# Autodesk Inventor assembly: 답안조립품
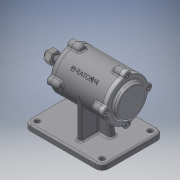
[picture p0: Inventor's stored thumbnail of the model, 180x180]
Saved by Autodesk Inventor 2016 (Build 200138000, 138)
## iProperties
Created: 2015-12
Part Number: 답안조립품
Document SubType Name: Assembly
Designer: Administrator
Author: Administrator
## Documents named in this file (11)
- D:\451208V1021\451208V1021\답안조립품.iam
- D:\451208V1021\451208V1021\본체.ipt
- D:\451208V1021\451208V1021\축.ipt
- D:\451208V1021\451208V1021\키(4 x 4 x 12).ipt
- D:\451208V1021\451208V1021\V-벨트풀리.ipt
- D:\451208V1021\451208V1021\너트 M12x1.25.ipt
- D:\451208V1021\451208V1021\베어링 6204.ipt
- D:\451208V1021\451208V1021\커버.ipt
- D:\451208V1021\451208V1021\오일실.ipt
- D:\451208V1021\451208V1021\커버2.ipt
- D:\451208V1021\451208V1021\볼트 M4 x 12.ipt
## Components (6 placed, 5 different names)
1. KS B 1311 (I) 4 x 4 x 12:1
2. V-벨트풀리:1
3. KS B 1012 클래스 1 일반 - 미터 M12x1.25:1
4. KS B 2023 6204 - 20 x 47 x 14:1
5. KS B 2023 6204 - 20 x 47 x 14:2
6. KS B 2804 D D - 20 32 8:1
